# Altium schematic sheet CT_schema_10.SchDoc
size 278 x 170 mm
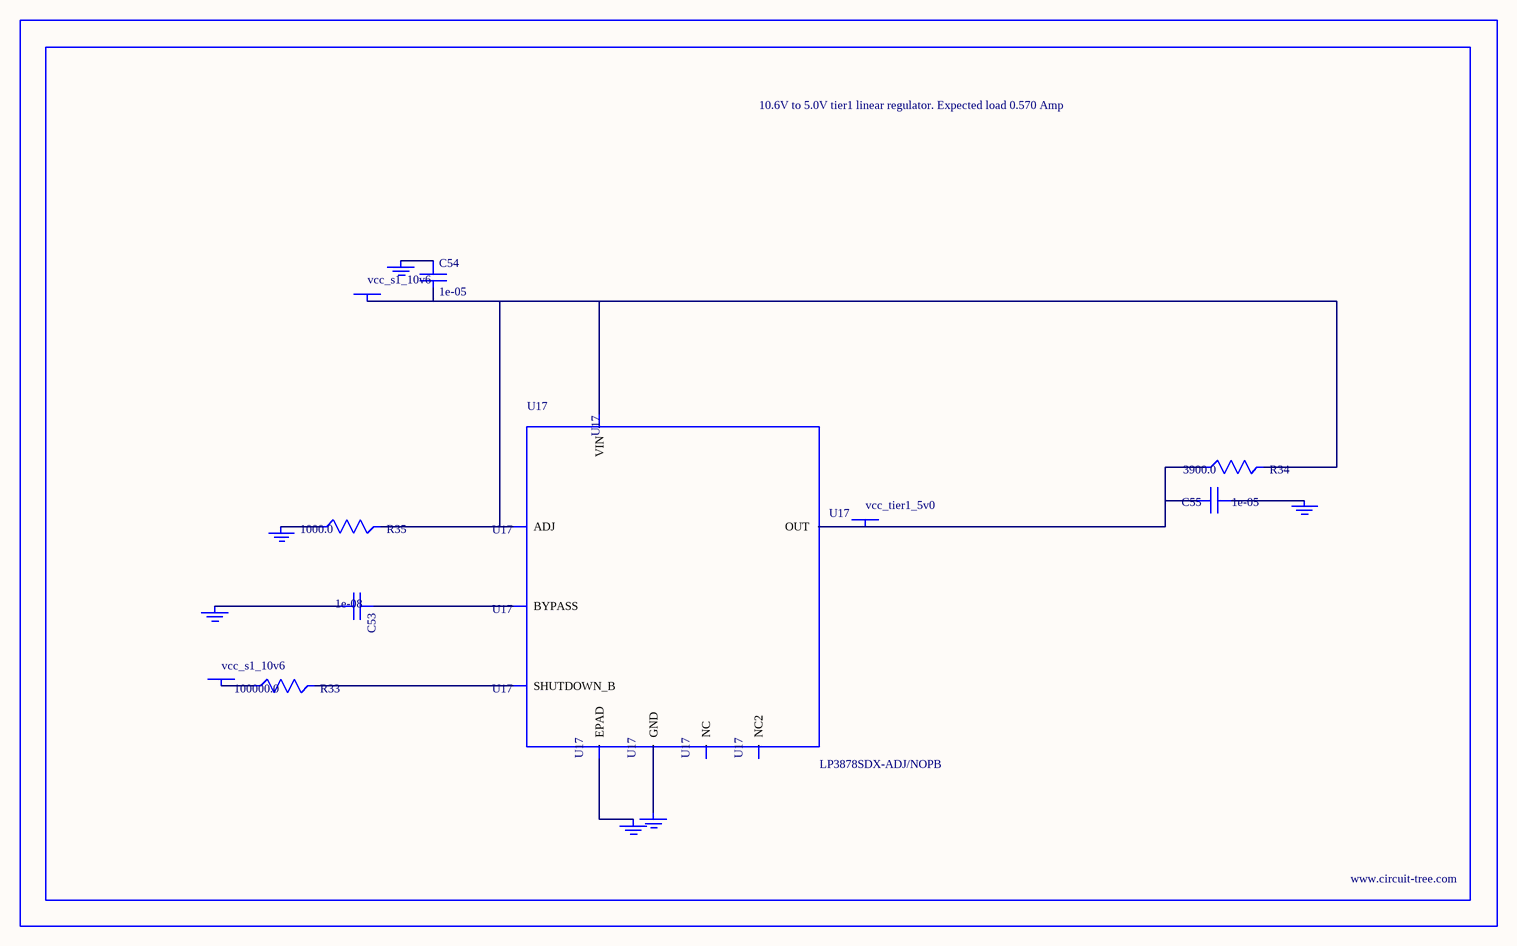
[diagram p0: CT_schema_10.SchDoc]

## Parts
BORDER9  (no value)
C53  1e-08  [C0402]
C54  1e-05  [C1206]
C55  1e-05  [C1210]
GND_INSTANCE_9_0  (no value)
GND_INSTANCE_9_1  (no value)
GND_INSTANCE_9_2  (no value)
GND_INSTANCE_9_3  (no value)
GND_INSTANCE_9_4  (no value)
GND_INSTANCE_9_5  (no value)
POWER_INSTANCE_9_0  vcc_s1_10v6
POWER_INSTANCE_9_1  vcc_s1_10v6
POWER_INSTANCE_9_2  vcc_tier1_5v0
R33  100000.0  [R0603]
R34  3900.0  [R0603]
R35  1000.0  [R0603]
U17  LP3878SDX-ADJ/NOPB  [WSON-8]

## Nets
NetC53_1: C53.1 U17.1(BYPASS)
NetC53_2: C53.2 GND_INSTANCE_9_0.0(GND)
NetC54_1: C54.1 GND_INSTANCE_9_1.0(GND)
NetC54_2: C54.2 POWER_INSTANCE_9_0.0(PWR) R34.2 R35.2 U17.4(VIN) U17.6(ADJ)
NetC55_1: C55.1 GND_INSTANCE_9_2.0(GND)
NetC55_2: C55.2 POWER_INSTANCE_9_2.0(PWR) R34.1 U17.5(OUT)
NetGND_INSTANCE_9_3_0: GND_INSTANCE_9_3.0(GND) R35.1
NetGND_INSTANCE_9_4_0: GND_INSTANCE_9_4.0(GND) U17.PAD(EPAD)
NetGND_INSTANCE_9_5_0: GND_INSTANCE_9_5.0(GND) U17.3(GND)
NetPOWER_INSTANCE_9_1_0: POWER_INSTANCE_9_1.0(PWR) R33.1
NetR33_2: R33.2 U17.8(SHUTDOWN_B)

Not connected (* = marked no-connect by the designer): U17 2(NC) 7(NC2)

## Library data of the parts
BORDER9 = BORDER_PAGE9
C53 = C0402C103K3RAC
C54 = C1206C106K3RACTU
C55 = GRM32DR61E106MA12L
GND_INSTANCE_9_0-GND_INSTANCE_9_5 = GND
POWER_INSTANCE_9_0-POWER_INSTANCE_9_2 = PWR
R33 = RC0603JR-07100KL
R34 = RC0603JR-073K9L
R35 = RC0603JR-071KL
